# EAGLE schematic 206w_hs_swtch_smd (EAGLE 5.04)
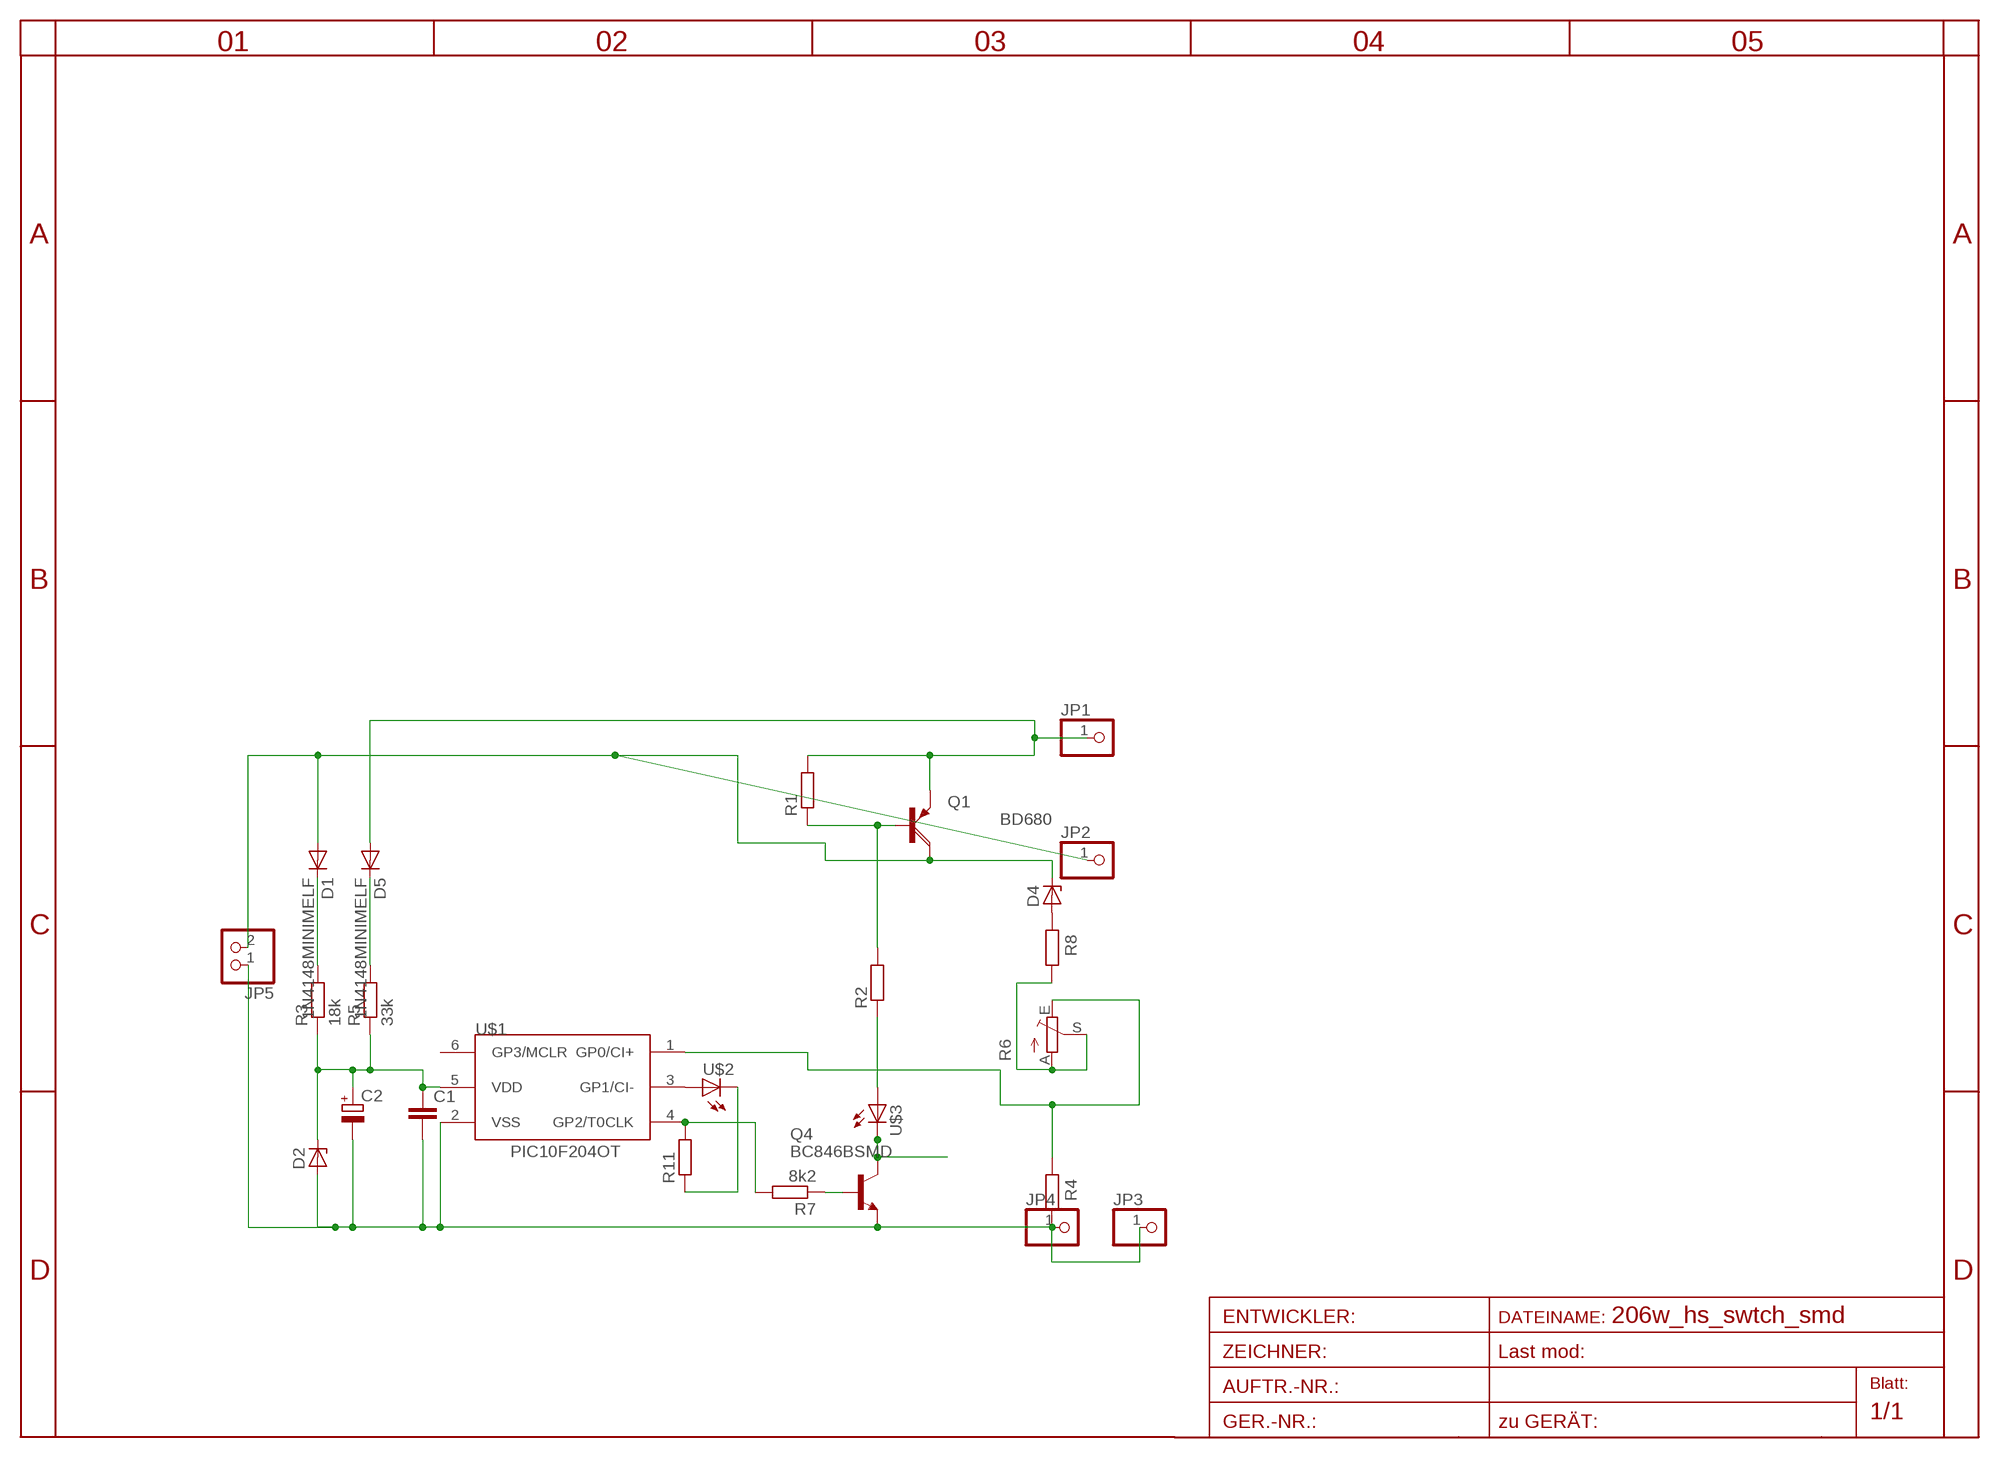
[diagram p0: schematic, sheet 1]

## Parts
C1  C-EUC0805  [C0805]
C2  CPOL-EUC  [PANASONIC_C]
D1  1N4148MINIMELF  [MINIMELF]
D2  ZENER-DIODESOT23  [SOT23]
D4  ZENER-DIODESMB  [SMB]
D5  1N4148MINIMELF  [MINIMELF]
JP1  PINHD-1X1  [1X01]
JP2  PINHD-1X1  [1X01]
JP3  PINHD-1X1  [1X01]
JP4  PINHD-1X1  [1X01]
JP5  PINHD-1X2  [1X02]
Q1  BD680  [TO126AV]
Q4  BC846BSMD  [SOT23]
R1  R-EU_R0805  [R0805]
R2  R-EU_R0805  [R0805]
R3  18k  R-EU_R0805  [R0805]
R4  R-EU_R0805  [R0805]
R5  33k  R-EU_R0805  [R0805]
R6  TRIM_EU-CA6V  [CA6V]
R7  8k2  R-EU_R0805  [R0805]
R8  R-EU_R0805  [R0805]
R11  R-EU_R0805  [R0805]
U$1  PIC10F204OT  [SOT23-6]
U$2  LED3MM  [LED3MM]
U$3  LED3MM  [LED3MM]

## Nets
GND: C1.2 C2.- D2.1(A) JP3.1 JP4.1 JP5.1 Q4.2(E) R4.1 U$1.2(VSS)
N$1: D4.A R8.2
N$2: C1.1 C2.+ D2.3(C) R3.1 R5.1 U$1.5(VDD)
N$3: D1.C R3.2
N$4: D5.C R5.2
N$5: U$1.3(GP1/CI-) U$2.A
N$6: R11.1 U$2.K(C)
N$7: R4.2 R6.E U$1.1(GP0/CI+)
N$8: R6.A R6.S R8.1
N$9: R7.2 R11.2 U$1.4(GP2/T0CLK)
N$10: Q4.1(B) R7.1
N$12: Q4.3(C) U$3.K(C)
N$13: Q1.B R1.1 R2.2
N$15: R2.1 U$3.A
N$17: D5.A JP1.1 Q1.E R1.2
V60: D1.A D4.C JP2.1 JP5.2 Q1.C
Unconnected: U$1.6(GP3/MCLR)

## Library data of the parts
C1 = rcl:C-EU: CAPACITOR, European symbol
C2 = rcl:CPOL-EU: POLARIZED CAPACITOR, European symbol
D1 D5 = diode-1:1N4148: DIODE
D2 D4 = diode-1:ZENER-DIODE: Z-Diode
JP1-JP4 = pinhead:PINHD-1X1: PIN HEADER
JP5 = pinhead:PINHD-1X2: PIN HEADER
Q1 = transistor-power:BD680: PNP DARLINGTON TRANSISTOR
Q4 = transistor-npn:BC846*: NPN Transistor
R1-R5 R7 R8 R11 = rcl:R-EU_: RESISTOR, European symbol
R6 = pot:TRIM_EU-: POTENTIOMETER
U$1 = microchip-5:PIC10F2*: uPC nW 0,25/0,5k Program Flash memory Comparator
U$2 U$3 = led(2):LED: LED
